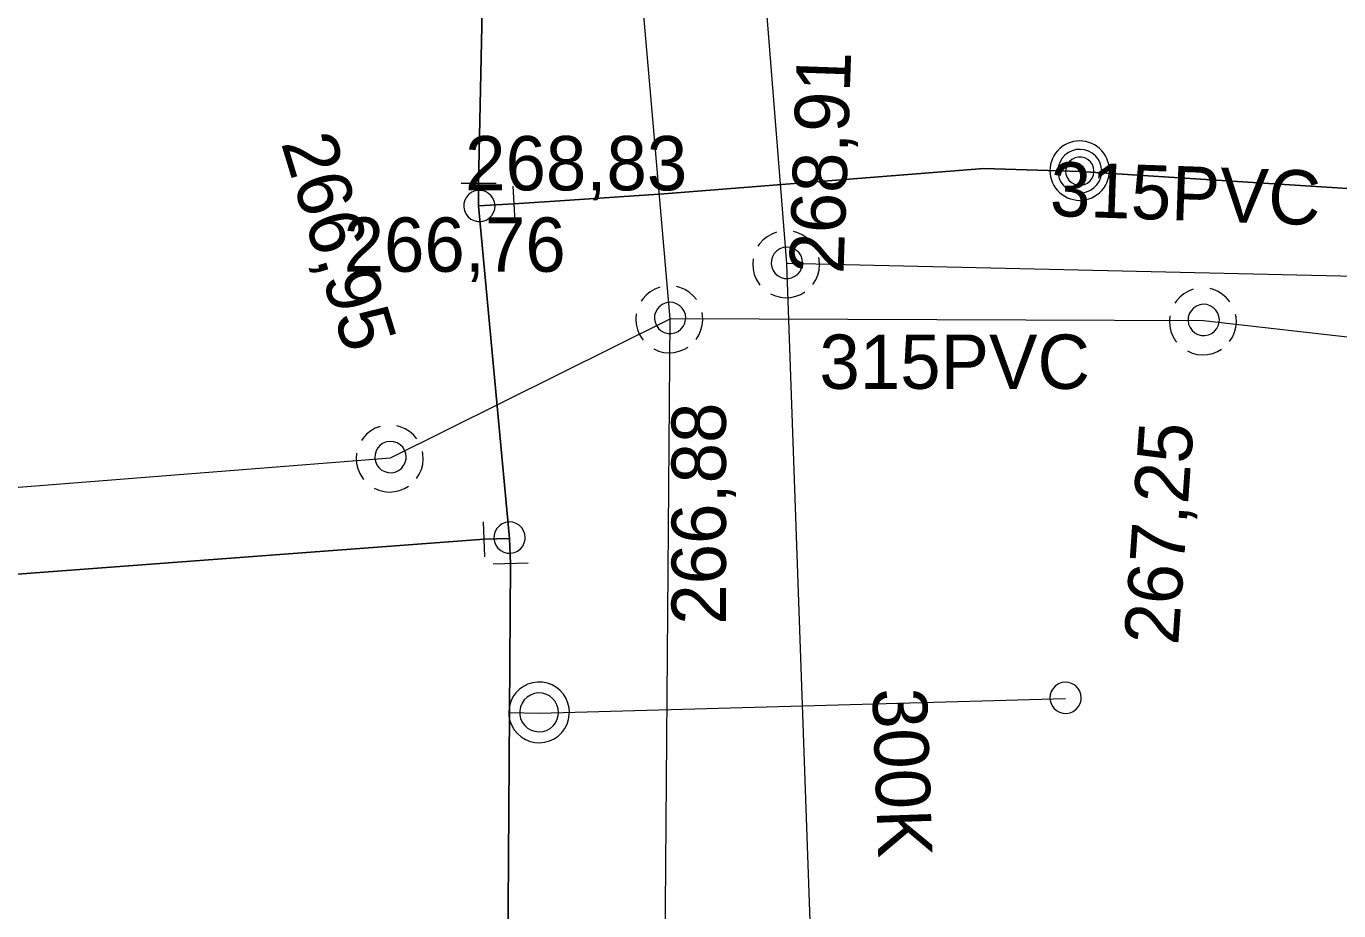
# Model space of a CAD drawing. Extents: x -732096 to -731933, y -1048703 to -1047964.
# Drawn here: x -731994.1 to -731974.77, y -1048647.16 to -1048634.13 of the extents above; entities that cross this region are included whole.
import ezdxf

# ---------------------------------------------------------------- set-up
doc = ezdxf.new("R2010")
doc.units = 0
doc.header["$LTSCALE"] = 0.32
doc.layers.add('1', color=7, linetype='Continuous')
for name, color, linetype, lineweight in [('18', 7, 'Continuous', 13), ('20', 7, 'Continuous', 13), ('8', 7, 'Continuous', 13)]:
    doc.layers.add(name, color=color, linetype=linetype, lineweight=lineweight)

msp = doc.modelspace()

# ---------------------------------------------------------------- linework, layer by layer
at = {"layer": '18'}
for points in [[(-731983.052, -1048637.166), (-731983.123, -1048637.194), (-731983.19, -1048637.233), (-731983.25, -1048637.281), (-731983.301, -1048637.338), (-731983.325, -1048637.372)], [(-731982.511, -1048637.349), (-731982.561, -1048637.291), (-731982.619, -1048637.241), (-731982.684, -1048637.2), (-731982.755, -1048637.171), (-731982.804, -1048637.157)], [(-731983.397, -1048637.558), (-731983.402, -1048637.635), (-731983.397, -1048637.712), (-731983.38, -1048637.787), (-731983.352, -1048637.858), (-731983.311, -1048637.924), (-731983.296, -1048637.946)], [(-731982.516, -1048637.935), (-731982.475, -1048637.87), (-731982.444, -1048637.8), (-731982.424, -1048637.725), (-731982.417, -1048637.649), (-731982.422, -1048637.572), (-731982.428, -1048637.537)], [(-731984.232, -1048638.16), (-731984.282, -1048638.102), (-731984.34, -1048638.052), (-731984.405, -1048638.011), (-731984.476, -1048637.982), (-731984.525, -1048637.968)], [(-731984.773, -1048637.977), (-731984.844, -1048638.005), (-731984.911, -1048638.044), (-731984.971, -1048638.092), (-731985.022, -1048638.149), (-731985.046, -1048638.183)], [(-731983.139, -1048638.075), (-731983.069, -1048638.106), (-731982.994, -1048638.125), (-731982.918, -1048638.132), (-731982.841, -1048638.127), (-731982.766, -1048638.11), (-731982.694, -1048638.082), (-731982.634, -1048638.047)], [(-731976.913, -1048638.007), (-731976.984, -1048638.035), (-731977.051, -1048638.074), (-731977.111, -1048638.122), (-731977.162, -1048638.179), (-731977.186, -1048638.213)], [(-731976.372, -1048638.19), (-731976.422, -1048638.132), (-731976.48, -1048638.082), (-731976.545, -1048638.041), (-731976.616, -1048638.012), (-731976.665, -1048637.998)], [(-731984.237, -1048638.746), (-731984.196, -1048638.681), (-731984.165, -1048638.611), (-731984.146, -1048638.536), (-731984.138, -1048638.46), (-731984.143, -1048638.383), (-731984.149, -1048638.348)], [(-731985.118, -1048638.369), (-731985.124, -1048638.446), (-731985.119, -1048638.523), (-731985.102, -1048638.598), (-731985.073, -1048638.669), (-731985.032, -1048638.735), (-731985.017, -1048638.757)], [(-731977.258, -1048638.399), (-731977.264, -1048638.476), (-731977.259, -1048638.553), (-731977.242, -1048638.628), (-731977.213, -1048638.699), (-731977.173, -1048638.765), (-731977.157, -1048638.787)], [(-731976.377, -1048638.776), (-731976.336, -1048638.711), (-731976.305, -1048638.641), (-731976.286, -1048638.566), (-731976.278, -1048638.49), (-731976.283, -1048638.413), (-731976.289, -1048638.378)], [(-731984.86, -1048638.886), (-731984.79, -1048638.917), (-731984.715, -1048638.936), (-731984.639, -1048638.943), (-731984.562, -1048638.938), (-731984.487, -1048638.921), (-731984.415, -1048638.893), (-731984.355, -1048638.858)], [(-731977, -1048638.916), (-731976.93, -1048638.947), (-731976.855, -1048638.966), (-731976.779, -1048638.973), (-731976.702, -1048638.968), (-731976.627, -1048638.951), (-731976.555, -1048638.923), (-731976.495, -1048638.888)], [(-731988.892, -1048640.027), (-731988.963, -1048640.055), (-731989.029, -1048640.094), (-731989.09, -1048640.142), (-731989.141, -1048640.199), (-731989.164, -1048640.233)], [(-731988.35, -1048640.21), (-731988.401, -1048640.152), (-731988.458, -1048640.102), (-731988.524, -1048640.061), (-731988.595, -1048640.032), (-731988.644, -1048640.018)], [(-731989.237, -1048640.419), (-731989.242, -1048640.496), (-731989.237, -1048640.573), (-731989.22, -1048640.648), (-731989.191, -1048640.719), (-731989.151, -1048640.785), (-731989.136, -1048640.807)], [(-731988.355, -1048640.796), (-731988.315, -1048640.731), (-731988.284, -1048640.661), (-731988.264, -1048640.586), (-731988.257, -1048640.51), (-731988.262, -1048640.433), (-731988.267, -1048640.398)], [(-731988.978, -1048640.936), (-731988.909, -1048640.967), (-731988.833, -1048640.986), (-731988.757, -1048640.993), (-731988.681, -1048640.988), (-731988.605, -1048640.971), (-731988.534, -1048640.943), (-731988.473, -1048640.908)]]:
    msp.add_lwpolyline(points, dxfattribs=at)
for points in [[(-731982.668, -1048637.618), (-731982.674, -1048637.566), (-731982.691, -1048637.516), (-731982.72, -1048637.472), (-731982.758, -1048637.435), (-731982.803, -1048637.408), (-731982.853, -1048637.392), (-731982.905, -1048637.387), (-731982.956, -1048637.394), (-731983.005, -1048637.413), (-731983.049, -1048637.443), (-731983.085, -1048637.482), (-731983.111, -1048637.527), (-731983.125, -1048637.578), (-731983.129, -1048637.63), (-731983.12, -1048637.682), (-731983.1, -1048637.73), (-731983.07, -1048637.773), (-731983.03, -1048637.808), (-731982.983, -1048637.832), (-731982.933, -1048637.846), (-731982.88, -1048637.848), (-731982.829, -1048637.838), (-731982.781, -1048637.816), (-731982.739, -1048637.784), (-731982.706, -1048637.744), (-731982.682, -1048637.697), (-731982.669, -1048637.646)], [(-731984.389, -1048638.429), (-731984.395, -1048638.377), (-731984.413, -1048638.327), (-731984.441, -1048638.283), (-731984.479, -1048638.246), (-731984.524, -1048638.219), (-731984.574, -1048638.203), (-731984.626, -1048638.198), (-731984.678, -1048638.205), (-731984.727, -1048638.224), (-731984.771, -1048638.254), (-731984.806, -1048638.293), (-731984.832, -1048638.338), (-731984.847, -1048638.389), (-731984.85, -1048638.441), (-731984.842, -1048638.493), (-731984.821, -1048638.541), (-731984.791, -1048638.584), (-731984.751, -1048638.619), (-731984.705, -1048638.643), (-731984.654, -1048638.657), (-731984.602, -1048638.659), (-731984.55, -1048638.649), (-731984.502, -1048638.627), (-731984.46, -1048638.595), (-731984.427, -1048638.555), (-731984.403, -1048638.508), (-731984.391, -1048638.457)], [(-731976.529, -1048638.459), (-731976.535, -1048638.407), (-731976.553, -1048638.357), (-731976.581, -1048638.313), (-731976.619, -1048638.276), (-731976.664, -1048638.249), (-731976.714, -1048638.233), (-731976.766, -1048638.228), (-731976.818, -1048638.235), (-731976.867, -1048638.254), (-731976.911, -1048638.284), (-731976.946, -1048638.323), (-731976.972, -1048638.368), (-731976.987, -1048638.419), (-731976.99, -1048638.471), (-731976.982, -1048638.523), (-731976.961, -1048638.571), (-731976.931, -1048638.614), (-731976.891, -1048638.649), (-731976.845, -1048638.673), (-731976.794, -1048638.687), (-731976.742, -1048638.689), (-731976.69, -1048638.679), (-731976.642, -1048638.657), (-731976.6, -1048638.625), (-731976.567, -1048638.585), (-731976.543, -1048638.538), (-731976.531, -1048638.487)], [(-731988.507, -1048640.479), (-731988.514, -1048640.427), (-731988.531, -1048640.377), (-731988.559, -1048640.333), (-731988.598, -1048640.296), (-731988.642, -1048640.269), (-731988.693, -1048640.253), (-731988.745, -1048640.248), (-731988.796, -1048640.255), (-731988.845, -1048640.274), (-731988.889, -1048640.304), (-731988.924, -1048640.343), (-731988.951, -1048640.388), (-731988.965, -1048640.439), (-731988.968, -1048640.491), (-731988.96, -1048640.543), (-731988.94, -1048640.591), (-731988.909, -1048640.634), (-731988.87, -1048640.669), (-731988.823, -1048640.693), (-731988.772, -1048640.707), (-731988.72, -1048640.709), (-731988.669, -1048640.699), (-731988.62, -1048640.677), (-731988.578, -1048640.645), (-731988.546, -1048640.605), (-731988.522, -1048640.558), (-731988.509, -1048640.507)]]:
    msp.add_lwpolyline(points, close=True, dxfattribs=at)
at = {"layer": '20'}
for p, q in [((-731982.21, -1048657.129), (-731982.899, -1048637.629)), ((-731982.21, -1048657.129), (-731982.899, -1048637.629)), ((-731988.739, -1048640.49), (-731984.62, -1048638.44)), ((-731988.739, -1048640.49), (-731984.62, -1048638.44)), ((-731976.76, -1048638.47), (-731984.62, -1048638.44)), ((-731976.76, -1048638.47), (-731984.62, -1048638.44)), ((-731959.989, -1048640.379), (-731976.76, -1048638.47)), ((-731959.989, -1048640.379), (-731976.76, -1048638.47))]:
    msp.add_line(p, q, dxfattribs=at)
for points in [[(-731984.62, -1048638.44), (-731986.574, -1048615.933), (-731987.18, -1048608.96)], [(-731984.62, -1048638.44), (-731986.574, -1048615.933), (-731987.18, -1048608.96)], [(-731969.16, -1048637.94), (-731982.899, -1048637.629), (-731984.98, -1048611.47)], [(-731969.16, -1048637.94), (-731982.899, -1048637.629), (-731984.98, -1048611.47)], [(-731985, -1048686.94), (-731984.895, -1048673.539), (-731984.774, -1048658.239), (-731984.62, -1048638.44)], [(-731985, -1048686.94), (-731984.895, -1048673.539), (-731984.774, -1048658.239), (-731984.62, -1048638.44)], [(-732038.379, -1048644.409), (-732026.322, -1048643.458), (-732025.923, -1048643.426), (-732011.07, -1048642.253), (-732004.989, -1048641.773), (-731988.739, -1048640.49)], [(-732038.379, -1048644.409), (-732026.322, -1048643.458), (-732025.923, -1048643.426), (-732011.07, -1048642.253), (-732004.989, -1048641.773), (-731988.739, -1048640.49)]]:
    msp.add_lwpolyline(points, dxfattribs=at)
at = {"layer": '8'}
for p, q in [((-731987.18, -1048636.45), (-731987.697, -1048636.449)), ((-731986.934, -1048636.49), (-731986.905, -1048637.007)), ((-731987.348, -1048641.949), (-731987.369, -1048641.432)), ((-731986.709, -1048642.039), (-731987.226, -1048642.058)), ((-731986.55, -1048644.25), (-731978.795, -1048644.036)), ((-731986.984, -1048644.243), (-731986.55, -1048644.25))]:
    msp.add_line(p, q, dxfattribs=at)
at = {"layer": '8', "lineweight": 25}
for p, q in [((-731987.44, -1048636.78), (-731986.92, -1048636.75)), ((-731986.984, -1048641.676), (-731986.969, -1048642.05))]:
    msp.add_line(p, q, dxfattribs=at)
for points in [[(-731990.289, -1048609.03), (-731989.399, -1048614.955), (-731989.079, -1048616.929), (-731987.35, -1048632.04), (-731987.44, -1048636.45)], [(-731986.92, -1048636.75), (-731986.62, -1048636.73), (-731986.32, -1048636.71), (-731984.71, -1048636.6), (-731980, -1048636.23), (-731978.579, -1048636.27)], [(-731978.579, -1048636.27), (-731974.02, -1048636.56), (-731968.19, -1048637.159), (-731956.25, -1048638.6), (-731946.058, -1048639.529)], [(-731987.44, -1048636.45), (-731987.44, -1048636.78), (-731986.984, -1048641.676), (-731987.359, -1048641.69)], [(-731987.359, -1048641.69), (-731999.541, -1048642.603), (-732003.1, -1048642.87), (-732015.815, -1048643.876), (-732022.8, -1048644.429), (-732022.922, -1048644.438), (-732027.789, -1048644.76), (-732037.579, -1048645.399)], [(-731986.969, -1048642.05), (-731986.984, -1048644.243), (-731987.12, -1048663.55), (-731987.35, -1048670.27), (-731987.388, -1048681.801), (-731987.43, -1048684.57)]]:
    msp.add_lwpolyline(points, dxfattribs=at)
at = {"layer": '8'}
msp.add_lwpolyline([(-731978.149, -1048636.259), (-731978.151, -1048636.214), (-731978.158, -1048636.169), (-731978.17, -1048636.124), (-731978.186, -1048636.082), (-731978.207, -1048636.041), (-731978.232, -1048636.002), (-731978.261, -1048635.967), (-731978.293, -1048635.934), (-731978.329, -1048635.906), (-731978.367, -1048635.881), (-731978.408, -1048635.86), (-731978.451, -1048635.843), (-731978.495, -1048635.831), (-731978.54, -1048635.824), (-731978.586, -1048635.822), (-731978.632, -1048635.824), (-731978.677, -1048635.831), (-731978.721, -1048635.843), (-731978.764, -1048635.86), (-731978.805, -1048635.881), (-731978.843, -1048635.906), (-731978.879, -1048635.934), (-731978.911, -1048635.967), (-731978.94, -1048636.002), (-731978.965, -1048636.041), (-731978.986, -1048636.082), (-731979.002, -1048636.124), (-731979.014, -1048636.169), (-731979.021, -1048636.214), (-731979.024, -1048636.26), (-731979.021, -1048636.305), (-731979.014, -1048636.35), (-731979.002, -1048636.395), (-731978.986, -1048636.437), (-731978.965, -1048636.478), (-731978.94, -1048636.517), (-731978.911, -1048636.552), (-731978.879, -1048636.585), (-731978.843, -1048636.613), (-731978.805, -1048636.638), (-731978.764, -1048636.659), (-731978.721, -1048636.676), (-731978.677, -1048636.687), (-731978.632, -1048636.695), (-731978.586, -1048636.697), (-731978.54, -1048636.695), (-731978.495, -1048636.687), (-731978.451, -1048636.676), (-731978.408, -1048636.659), (-731978.367, -1048636.638), (-731978.329, -1048636.613), (-731978.293, -1048636.585), (-731978.261, -1048636.552), (-731978.232, -1048636.517), (-731978.207, -1048636.478), (-731978.186, -1048636.437), (-731978.17, -1048636.395), (-731978.158, -1048636.35), (-731978.151, -1048636.305), (-731978.149, -1048636.26)], dxfattribs=at)
for points in [[(-731978.262, -1048636.267), (-731978.268, -1048636.206), (-731978.286, -1048636.146), (-731978.315, -1048636.091), (-731978.354, -1048636.043), (-731978.401, -1048636.003), (-731978.455, -1048635.973), (-731978.514, -1048635.953), (-731978.576, -1048635.946), (-731978.638, -1048635.95), (-731978.698, -1048635.966), (-731978.753, -1048635.994), (-731978.803, -1048636.031), (-731978.844, -1048636.078), (-731978.876, -1048636.131), (-731978.896, -1048636.19), (-731978.906, -1048636.251), (-731978.903, -1048636.313), (-731978.888, -1048636.373), (-731978.862, -1048636.43), (-731978.826, -1048636.48), (-731978.78, -1048636.523), (-731978.728, -1048636.555), (-731978.67, -1048636.578), (-731978.609, -1048636.588), (-731978.547, -1048636.587), (-731978.486, -1048636.574), (-731978.429, -1048636.549), (-731978.378, -1048636.514), (-731978.334, -1048636.47), (-731978.3, -1048636.418), (-731978.276, -1048636.361), (-731978.264, -1048636.3)], [(-731978.376, -1048636.267), (-731978.382, -1048636.218), (-731978.399, -1048636.171), (-731978.427, -1048636.13), (-731978.465, -1048636.097), (-731978.509, -1048636.073), (-731978.557, -1048636.061), (-731978.607, -1048636.06), (-731978.655, -1048636.072), (-731978.7, -1048636.094), (-731978.738, -1048636.127), (-731978.767, -1048636.167), (-731978.786, -1048636.214), (-731978.793, -1048636.263), (-731978.788, -1048636.313), (-731978.771, -1048636.36), (-731978.744, -1048636.402), (-731978.707, -1048636.436), (-731978.664, -1048636.46), (-731978.616, -1048636.474), (-731978.566, -1048636.475), (-731978.517, -1048636.465), (-731978.472, -1048636.443), (-731978.433, -1048636.411), (-731978.403, -1048636.372), (-731978.384, -1048636.326), (-731978.376, -1048636.276)], [(-731987.429, -1048637.011), (-731987.377, -1048637.005), (-731987.327, -1048636.987), (-731987.283, -1048636.959), (-731987.246, -1048636.921), (-731987.219, -1048636.876), (-731987.203, -1048636.826), (-731987.198, -1048636.774), (-731987.205, -1048636.722), (-731987.224, -1048636.673), (-731987.254, -1048636.629), (-731987.293, -1048636.594), (-731987.338, -1048636.568), (-731987.389, -1048636.553), (-731987.441, -1048636.55), (-731987.493, -1048636.557), (-731987.541, -1048636.578), (-731987.584, -1048636.608), (-731987.619, -1048636.648), (-731987.643, -1048636.694), (-731987.657, -1048636.745), (-731987.659, -1048636.797), (-731987.649, -1048636.849), (-731987.627, -1048636.897), (-731987.595, -1048636.939), (-731987.555, -1048636.972), (-731987.508, -1048636.996), (-731987.457, -1048637.008)], [(-731986.753, -1048641.665), (-731986.759, -1048641.613), (-731986.777, -1048641.563), (-731986.805, -1048641.519), (-731986.843, -1048641.482), (-731986.888, -1048641.455), (-731986.938, -1048641.439), (-731986.99, -1048641.434), (-731987.042, -1048641.441), (-731987.091, -1048641.46), (-731987.135, -1048641.49), (-731987.17, -1048641.529), (-731987.196, -1048641.574), (-731987.211, -1048641.625), (-731987.214, -1048641.677), (-731987.206, -1048641.729), (-731987.185, -1048641.777), (-731987.155, -1048641.82), (-731987.115, -1048641.855), (-731987.069, -1048641.879), (-731987.018, -1048641.893), (-731986.966, -1048641.895), (-731986.914, -1048641.885), (-731986.866, -1048641.863), (-731986.824, -1048641.831), (-731986.791, -1048641.791), (-731986.767, -1048641.744), (-731986.755, -1048641.693)], [(-731986.102, -1048644.246), (-731986.107, -1048644.173), (-731986.124, -1048644.102), (-731986.152, -1048644.034), (-731986.191, -1048643.973), (-731986.239, -1048643.917), (-731986.295, -1048643.871), (-731986.359, -1048643.835), (-731986.427, -1048643.809), (-731986.499, -1048643.795), (-731986.573, -1048643.793), (-731986.645, -1048643.802), (-731986.716, -1048643.824), (-731986.78, -1048643.856), (-731986.84, -1048643.899), (-731986.892, -1048643.951), (-731986.934, -1048644.011), (-731986.966, -1048644.077), (-731986.987, -1048644.147), (-731986.996, -1048644.22), (-731986.993, -1048644.293), (-731986.978, -1048644.364), (-731986.953, -1048644.433), (-731986.916, -1048644.496), (-731986.868, -1048644.552), (-731986.813, -1048644.6), (-731986.751, -1048644.638), (-731986.683, -1048644.666), (-731986.611, -1048644.682), (-731986.539, -1048644.686), (-731986.465, -1048644.678), (-731986.395, -1048644.659), (-731986.329, -1048644.628), (-731986.268, -1048644.587), (-731986.215, -1048644.536), (-731986.171, -1048644.477), (-731986.137, -1048644.413), (-731986.115, -1048644.343), (-731986.104, -1048644.271)], [(-731986.263, -1048644.244), (-731986.268, -1048644.186), (-731986.286, -1048644.129), (-731986.313, -1048644.078), (-731986.351, -1048644.033), (-731986.396, -1048643.996), (-731986.449, -1048643.971), (-731986.506, -1048643.956), (-731986.565, -1048643.953), (-731986.622, -1048643.962), (-731986.677, -1048643.983), (-731986.727, -1048644.014), (-731986.768, -1048644.054), (-731986.801, -1048644.103), (-731986.824, -1048644.158), (-731986.835, -1048644.214), (-731986.834, -1048644.273), (-731986.821, -1048644.331), (-731986.797, -1048644.384), (-731986.761, -1048644.431), (-731986.718, -1048644.47), (-731986.668, -1048644.499), (-731986.612, -1048644.518), (-731986.554, -1048644.525), (-731986.496, -1048644.52), (-731986.44, -1048644.504), (-731986.388, -1048644.476), (-731986.344, -1048644.437), (-731986.308, -1048644.392), (-731986.282, -1048644.339), (-731986.267, -1048644.283)], [(-731978.563, -1048644.029), (-731978.569, -1048643.977), (-731978.586, -1048643.926), (-731978.613, -1048643.882), (-731978.65, -1048643.844), (-731978.695, -1048643.817), (-731978.745, -1048643.8), (-731978.797, -1048643.794), (-731978.849, -1048643.8), (-731978.898, -1048643.818), (-731978.942, -1048643.848), (-731978.978, -1048643.886), (-731979.005, -1048643.931), (-731979.021, -1048643.981), (-731979.024, -1048644.033), (-731979.017, -1048644.085), (-731978.997, -1048644.134), (-731978.968, -1048644.177), (-731978.928, -1048644.213), (-731978.883, -1048644.238), (-731978.832, -1048644.252), (-731978.78, -1048644.255), (-731978.728, -1048644.246), (-731978.68, -1048644.225), (-731978.637, -1048644.194), (-731978.603, -1048644.154), (-731978.579, -1048644.108), (-731978.566, -1048644.057)]]:
    msp.add_lwpolyline(points, close=True, dxfattribs=at)

# ---------------------------------------------------------------- texts
at = {"layer": '1'}
for s, rotation, p in [('268,91', 88, (-731982.066, -1048637.786)), ('266,95', 287, (-731990.354, -1048635.85)), ('315PVC', 358, (-731979.032, -1048636.925)), ('266,88', 90, (-731983.798, -1048642.948)), ('267,25', 86, (-731977.136, -1048643.26)), ('300K', 272, (-731981.64, -1048643.893))]:
    msp.add_text(s, height=0.8, rotation=rotation, dxfattribs=at).set_placement(p)
for s, p in [('268,83', (-731987.639, -1048636.55)), ('266,76', (-731989.429, -1048637.749)), ('315PVC', (-731982.42, -1048639.474))]:
    msp.add_text(s, height=0.8, dxfattribs=at).set_placement(p)

doc.saveas('drawing.dxf')
